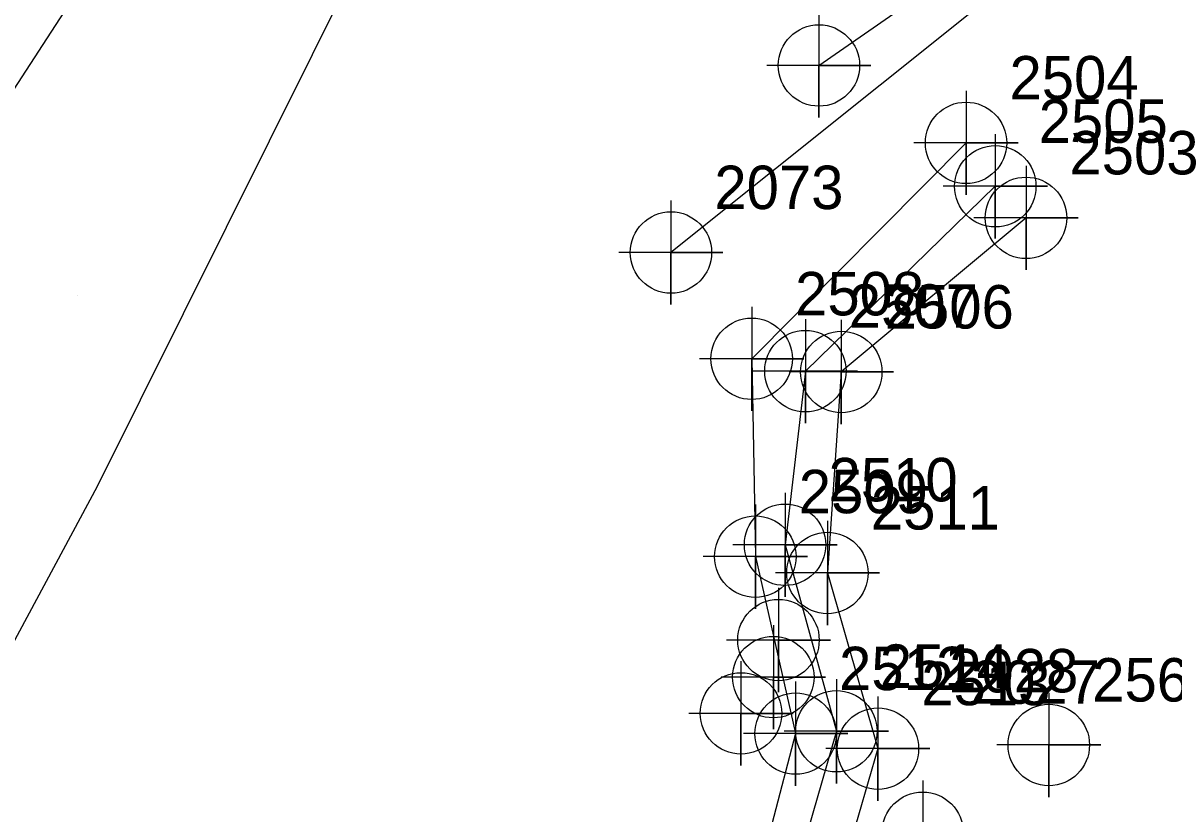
# Model space of a CAD drawing. Extents: x 2062781 to 2066835, y 358981 to 366501.
# Drawn here: x 2064112 to 2064178.3, y 361425.6 to 361471.1 of the extents above; entities that cross this region are included whole.
import ezdxf

# ---------------------------------------------------------------- set-up
doc = ezdxf.new("R2010")
doc.units = 0
for name, color, linetype in [('Exist DTM Breakline', 7, 'Continuous'), ('Exist DTM Breakline Cogo Number', 7, 'Continuous'), ('Exist DTM Breakline Cogo Point CELL', 7, 'Continuous'), ('Exist DTM Regular Point CELL', 7, 'Continuous'), ('Exist DTM Regular Point Cogo Number', 7, 'Continuous'), ('Exist DTM Ridgeline', 7, 'Continuous'), ('Exist DTM Ridgeline Cogo Number', 7, 'Continuous'), ('Exist DTM Ridgeline Cogo Point CELL', 7, 'Continuous'), ('PH Exist DTM Breakline', 7, 'Continuous'), ('PH Exist DTM Point', 7, 'Continuous')]:
    doc.layers.add(name, color=color, linetype=linetype)

msp = doc.modelspace()

# ---------------------------------------------------------------- linework, layer by layer
at = {"layer": 'Exist DTM Breakline'}
for points in [[(2064179.522, 361482.066), (2064149.285, 361457.883)], [(2064167.966, 361461.696), (2064157.029, 361451.052), (2064155.86, 361441.057), (2064158.815, 361430.322), (2064155.475, 361418.752), (2064150.498, 361414.897), (2064143.512, 361411.198), (2064143.071, 361410.97)]]:
    msp.add_lwpolyline(points, dxfattribs=at)
at = {"layer": 'Exist DTM Breakline Cogo Point CELL'}
for points in [[(2064167.966, 361464.696), (2064167.966, 361458.696), (2064167.966, 361461.696), (2064170.966, 361461.696), (2064164.966, 361461.696)], [(2064167.966, 361464.696), (2064167.966, 361458.696), (2064167.966, 361461.696), (2064170.966, 361461.696), (2064164.966, 361461.696)], [(2064167.966, 361464.696), (2064167.966, 361458.696), (2064167.966, 361461.696), (2064170.966, 361461.696), (2064164.966, 361461.696)], [(2064149.285, 361460.883), (2064149.285, 361454.883), (2064149.285, 361457.883), (2064152.285, 361457.883), (2064146.285, 361457.883)], [(2064149.285, 361460.883), (2064149.285, 361454.883), (2064149.285, 361457.883), (2064152.285, 361457.883), (2064146.285, 361457.883)], [(2064149.285, 361460.883), (2064149.285, 361454.883), (2064149.285, 361457.883), (2064152.285, 361457.883), (2064146.285, 361457.883)], [(2064157.029, 361454.052), (2064157.029, 361448.052), (2064157.029, 361451.052), (2064160.029, 361451.052), (2064154.029, 361451.052)], [(2064157.029, 361454.052), (2064157.029, 361448.052), (2064157.029, 361451.052), (2064160.029, 361451.052), (2064154.029, 361451.052)], [(2064157.029, 361454.052), (2064157.029, 361448.052), (2064157.029, 361451.052), (2064160.029, 361451.052), (2064154.029, 361451.052)], [(2064155.86, 361444.057), (2064155.86, 361438.057), (2064155.86, 361441.057), (2064158.86, 361441.057), (2064152.86, 361441.057)], [(2064155.86, 361444.057), (2064155.86, 361438.057), (2064155.86, 361441.057), (2064158.86, 361441.057), (2064152.86, 361441.057)], [(2064155.86, 361444.057), (2064155.86, 361438.057), (2064155.86, 361441.057), (2064158.86, 361441.057), (2064152.86, 361441.057)], [(2064155.184, 361436.439), (2064155.184, 361430.439), (2064155.184, 361433.439), (2064158.184, 361433.439), (2064152.184, 361433.439)], [(2064155.184, 361436.439), (2064155.184, 361430.439), (2064155.184, 361433.439), (2064158.184, 361433.439), (2064152.184, 361433.439)], [(2064155.184, 361436.439), (2064155.184, 361430.439), (2064155.184, 361433.439), (2064158.184, 361433.439), (2064152.184, 361433.439)], [(2064158.815, 361433.322), (2064158.815, 361427.322), (2064158.815, 361430.322), (2064161.815, 361430.322), (2064155.815, 361430.322)], [(2064158.815, 361433.322), (2064158.815, 361427.322), (2064158.815, 361430.322), (2064161.815, 361430.322), (2064155.815, 361430.322)], [(2064158.815, 361433.322), (2064158.815, 361427.322), (2064158.815, 361430.322), (2064161.815, 361430.322), (2064155.815, 361430.322)]]:
    msp.add_lwpolyline(points, dxfattribs=at)
for centre in [(2064167.966, 361461.696), (2064167.966, 361461.696), (2064167.966, 361461.696), (2064149.285, 361457.883), (2064149.285, 361457.883), (2064149.285, 361457.883), (2064157.029, 361451.052), (2064157.029, 361451.052), (2064157.029, 361451.052), (2064155.86, 361441.057), (2064155.86, 361441.057), (2064155.86, 361441.057), (2064155.184, 361433.439), (2064155.184, 361433.439), (2064155.184, 361433.439), (2064158.815, 361430.322), (2064158.815, 361430.322), (2064158.815, 361430.322)]:
    msp.add_circle(centre, 2.344, dxfattribs=at)
at = {"layer": 'Exist DTM Regular Point CELL'}
msp.add_lwpolyline([(2064171.049, 361432.533), (2064171.049, 361426.533), (2064171.049, 361429.533), (2064174.049, 361429.533), (2064168.049, 361429.533)], dxfattribs=at)
msp.add_circle((2064171.049, 361429.533), 2.344, dxfattribs=at)
at = {"layer": 'Exist DTM Ridgeline'}
for points in [[(2064157.807, 361468.649), (2064179.351, 361483.587), (2064201.333, 361505.698)], [(2064166.284, 361464.194), (2064153.937, 361451.763), (2064154.149, 361440.373), (2064156.469, 361430.188), (2064153.73, 361419.763), (2064146.259, 361415.181), (2064143.239, 361413.354)], [(2064169.735, 361459.878), (2064159.096, 361451.006), (2064158.3, 361439.435), (2064161.205, 361429.321), (2064157.871, 361417.823), (2064155.941, 361407.27), (2064153.228, 361398.956), (2064148.684, 361390.313), (2064145.195, 361382.213), (2064137.715, 361382.492), (2064139.785, 361391.475), (2064142.629, 361400.022), (2064147.572, 361411.431), (2064143.136, 361409.601)]]:
    msp.add_lwpolyline(points, dxfattribs=at)
at = {"layer": 'Exist DTM Ridgeline Cogo Point CELL'}
for points in [[(2064157.807, 361471.649), (2064157.807, 361465.649), (2064157.807, 361468.649), (2064160.807, 361468.649), (2064154.807, 361468.649)], [(2064157.807, 361471.649), (2064157.807, 361465.649), (2064157.807, 361468.649), (2064160.807, 361468.649), (2064154.807, 361468.649)], [(2064157.807, 361471.649), (2064157.807, 361465.649), (2064157.807, 361468.649), (2064160.807, 361468.649), (2064154.807, 361468.649)], [(2064166.284, 361467.194), (2064166.284, 361461.194), (2064166.284, 361464.194), (2064169.284, 361464.194), (2064163.284, 361464.194)], [(2064166.284, 361467.194), (2064166.284, 361461.194), (2064166.284, 361464.194), (2064169.284, 361464.194), (2064163.284, 361464.194)], [(2064166.284, 361467.194), (2064166.284, 361461.194), (2064166.284, 361464.194), (2064169.284, 361464.194), (2064163.284, 361464.194)], [(2064169.735, 361462.878), (2064169.735, 361456.878), (2064169.735, 361459.878), (2064172.735, 361459.878), (2064166.735, 361459.878)], [(2064169.735, 361462.878), (2064169.735, 361456.878), (2064169.735, 361459.878), (2064172.735, 361459.878), (2064166.735, 361459.878)], [(2064169.735, 361462.878), (2064169.735, 361456.878), (2064169.735, 361459.878), (2064172.735, 361459.878), (2064166.735, 361459.878)], [(2064153.937, 361454.763), (2064153.937, 361448.763), (2064153.937, 361451.763), (2064156.937, 361451.763), (2064150.937, 361451.763)], [(2064153.937, 361454.763), (2064153.937, 361448.763), (2064153.937, 361451.763), (2064156.937, 361451.763), (2064150.937, 361451.763)], [(2064153.937, 361454.763), (2064153.937, 361448.763), (2064153.937, 361451.763), (2064156.937, 361451.763), (2064150.937, 361451.763)], [(2064159.096, 361454.006), (2064159.096, 361448.006), (2064159.096, 361451.006), (2064162.096, 361451.006), (2064156.096, 361451.006)], [(2064159.096, 361454.006), (2064159.096, 361448.006), (2064159.096, 361451.006), (2064162.096, 361451.006), (2064156.096, 361451.006)], [(2064159.096, 361454.006), (2064159.096, 361448.006), (2064159.096, 361451.006), (2064162.096, 361451.006), (2064156.096, 361451.006)], [(2064154.149, 361443.373), (2064154.149, 361437.373), (2064154.149, 361440.373), (2064157.149, 361440.373), (2064151.149, 361440.373)], [(2064154.149, 361443.373), (2064154.149, 361437.373), (2064154.149, 361440.373), (2064157.149, 361440.373), (2064151.149, 361440.373)], [(2064154.149, 361443.373), (2064154.149, 361437.373), (2064154.149, 361440.373), (2064157.149, 361440.373), (2064151.149, 361440.373)], [(2064158.3, 361442.435), (2064158.3, 361436.435), (2064158.3, 361439.435), (2064161.3, 361439.435), (2064155.3, 361439.435)], [(2064158.3, 361442.435), (2064158.3, 361436.435), (2064158.3, 361439.435), (2064161.3, 361439.435), (2064155.3, 361439.435)], [(2064158.3, 361442.435), (2064158.3, 361436.435), (2064158.3, 361439.435), (2064161.3, 361439.435), (2064155.3, 361439.435)], [(2064155.48, 361438.57), (2064155.48, 361432.57), (2064155.48, 361435.57), (2064158.48, 361435.57), (2064152.48, 361435.57)], [(2064155.48, 361438.57), (2064155.48, 361432.57), (2064155.48, 361435.57), (2064158.48, 361435.57), (2064152.48, 361435.57)], [(2064155.48, 361438.57), (2064155.48, 361432.57), (2064155.48, 361435.57), (2064158.48, 361435.57), (2064152.48, 361435.57)], [(2064153.321, 361434.35), (2064153.321, 361428.35), (2064153.321, 361431.35), (2064156.321, 361431.35), (2064150.321, 361431.35)], [(2064153.321, 361434.35), (2064153.321, 361428.35), (2064153.321, 361431.35), (2064156.321, 361431.35), (2064150.321, 361431.35)], [(2064153.321, 361434.35), (2064153.321, 361428.35), (2064153.321, 361431.35), (2064156.321, 361431.35), (2064150.321, 361431.35)], [(2064156.469, 361433.188), (2064156.469, 361427.188), (2064156.469, 361430.188), (2064159.469, 361430.188), (2064153.469, 361430.188)], [(2064156.469, 361433.188), (2064156.469, 361427.188), (2064156.469, 361430.188), (2064159.469, 361430.188), (2064153.469, 361430.188)], [(2064156.469, 361433.188), (2064156.469, 361427.188), (2064156.469, 361430.188), (2064159.469, 361430.188), (2064153.469, 361430.188)], [(2064161.205, 361432.321), (2064161.205, 361426.321), (2064161.205, 361429.321), (2064164.205, 361429.321), (2064158.205, 361429.321)], [(2064161.205, 361432.321), (2064161.205, 361426.321), (2064161.205, 361429.321), (2064164.205, 361429.321), (2064158.205, 361429.321)], [(2064161.205, 361432.321), (2064161.205, 361426.321), (2064161.205, 361429.321), (2064164.205, 361429.321), (2064158.205, 361429.321)], [(2064163.784, 361427.478), (2064163.784, 361421.478), (2064163.784, 361424.478), (2064166.784, 361424.478), (2064160.784, 361424.478)], [(2064163.784, 361427.478), (2064163.784, 361421.478), (2064163.784, 361424.478), (2064166.784, 361424.478), (2064160.784, 361424.478)], [(2064163.784, 361427.478), (2064163.784, 361421.478), (2064163.784, 361424.478), (2064166.784, 361424.478), (2064160.784, 361424.478)]]:
    msp.add_lwpolyline(points, dxfattribs=at)
for centre in [(2064157.807, 361468.649), (2064157.807, 361468.649), (2064157.807, 361468.649), (2064166.284, 361464.194), (2064166.284, 361464.194), (2064166.284, 361464.194), (2064169.735, 361459.878), (2064169.735, 361459.878), (2064169.735, 361459.878), (2064153.937, 361451.763), (2064153.937, 361451.763), (2064153.937, 361451.763), (2064159.096, 361451.006), (2064159.096, 361451.006), (2064159.096, 361451.006), (2064154.149, 361440.373), (2064154.149, 361440.373), (2064154.149, 361440.373), (2064158.3, 361439.435), (2064158.3, 361439.435), (2064158.3, 361439.435), (2064155.48, 361435.57), (2064155.48, 361435.57), (2064155.48, 361435.57), (2064153.321, 361431.35), (2064153.321, 361431.35), (2064153.321, 361431.35), (2064156.469, 361430.188), (2064156.469, 361430.188), (2064156.469, 361430.188), (2064161.205, 361429.321), (2064161.205, 361429.321), (2064161.205, 361429.321), (2064163.784, 361424.478), (2064163.784, 361424.478), (2064163.784, 361424.478)]:
    msp.add_circle(centre, 2.344, dxfattribs=at)
at = {"layer": 'PH Exist DTM Breakline'}
for points in [[(2064078.941, 361375.618), (2064096.39, 361407.467), (2064116.272, 361444.439), (2064133.606, 361479.232), (2064151.973, 361505.442), (2064160.76, 361518.208), (2064172.834, 361547.027), (2064190.561, 361582.129), (2064206.147, 361613.547), (2064218.65, 361638.457)], [(2064169.73, 361588.421), (2064160.776, 361570.227), (2064152.848, 361554.43), (2064145.223, 361539.239), (2064135.861, 361520.588), (2064131.171, 361511.243), (2064128.874, 361501.931), (2064127.814, 361496.654), (2064124.292, 361486.999), (2064113.821, 361470.956), (2064105.667, 361458.423), (2064101.064, 361449.809), (2064096.582, 361440.88), (2064094.206, 361431.846), (2064089.171, 361420.333), (2064084.102, 361412.172), (2064081.203, 361402.724), (2064079.126, 361400.31), (2064075.785, 361398.219), (2064073.627, 361396.707), (2064071.474, 361392.468), (2064069.936, 361385.095), (2064071.015, 361378.419), (2064070.798, 361376.416)]]:
    msp.add_lwpolyline(points, dxfattribs=at)
at = {"layer": 'PH Exist DTM Point'}
for p, q in [((2064115.111, 361455.395), (2064115.111, 361455.395)), ((2064176.879, 361432.713), (2064176.879, 361432.713))]:
    msp.add_line(p, q, dxfattribs=at)

# ---------------------------------------------------------------- texts
at = {"layer": 'Exist DTM Breakline Cogo Number'}
for s, p in [('2505', (2064170.466, 361464.196)), ('2505', (2064170.466, 361464.196)), ('2505', (2064170.466, 361464.196)), ('2073', (2064151.785, 361460.383)), ('2073', (2064151.785, 361460.383)), ('2073', (2064151.785, 361460.383)), ('2507', (2064159.529, 361453.552)), ('2507', (2064159.529, 361453.552)), ('2507', (2064159.529, 361453.552)), ('2510', (2064158.36, 361443.557)), ('2510', (2064158.36, 361443.557)), ('2510', (2064158.36, 361443.557)), ('2514', (2064161.315, 361432.822)), ('2514', (2064161.315, 361432.822)), ('2514', (2064161.315, 361432.822)), ('2028', (2064165.313, 361432.559)), ('2028', (2064165.313, 361432.559)), ('2028', (2064165.313, 361432.559)), ('2027', (2064166.561, 361431.902)), ('2027', (2064166.561, 361431.902)), ('2027', (2064166.561, 361431.902))]:
    msp.add_text(s, height=2.5, dxfattribs=at).set_placement(p)
at = {"layer": 'Exist DTM Regular Point Cogo Number'}
msp.add_text('2561', height=2.5, dxfattribs=at).set_placement((2064173.549, 361432.033))
msp.add_text('2561', height=2.5, dxfattribs=at).set_placement((2064173.549, 361432.033))
msp.add_text('2561', height=2.5, dxfattribs=at).set_placement((2064173.549, 361432.033))
at = {"layer": 'Exist DTM Ridgeline Cogo Number'}
for s, p in [('2504', (2064168.784, 361466.694)), ('2504', (2064168.784, 361466.694)), ('2504', (2064168.784, 361466.694)), ('2503', (2064172.235, 361462.378)), ('2503', (2064172.235, 361462.378)), ('2503', (2064172.235, 361462.378)), ('2508', (2064156.437, 361454.263)), ('2508', (2064156.437, 361454.263)), ('2508', (2064156.437, 361454.263)), ('2506', (2064161.596, 361453.506)), ('2506', (2064161.596, 361453.506)), ('2506', (2064161.596, 361453.506)), ('2509', (2064156.649, 361442.873)), ('2509', (2064156.649, 361442.873)), ('2509', (2064156.649, 361442.873)), ('2511', (2064160.8, 361441.935)), ('2511', (2064160.8, 361441.935)), ('2511', (2064160.8, 361441.935)), ('2512', (2064158.969, 361432.688)), ('2512', (2064158.969, 361432.688)), ('2512', (2064158.969, 361432.688)), ('2513', (2064163.705, 361431.821)), ('2513', (2064163.705, 361431.821)), ('2513', (2064163.705, 361431.821))]:
    msp.add_text(s, height=2.5, dxfattribs=at).set_placement(p)

doc.saveas('drawing.dxf')
